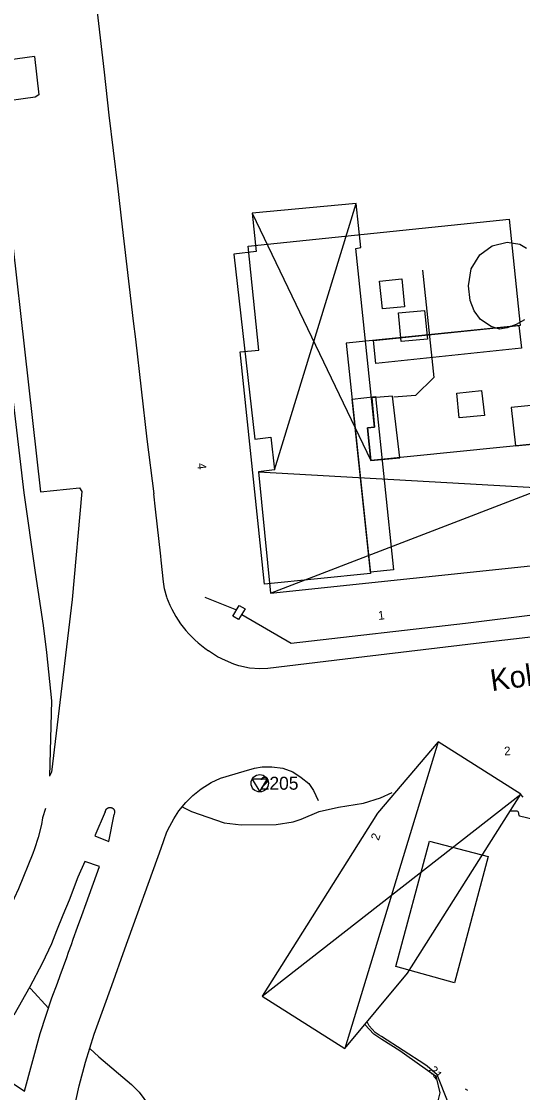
# Model space of a CAD drawing. Extents: x 67169 to 69652, y 20189 to 22818.
# Drawn here: x 69428.4 to 69486.1, y 21189.9 to 21313.4 of the extents above; entities that cross this region are included whole.
import ezdxf

# ---------------------------------------------------------------- set-up
doc = ezdxf.new("R2010")
doc.units = 0
for name, color, linetype in [('BYGGNAD_HUSLIV', 7, 'Continuous'), ('BYGGNAD_HUSLIV 13', 7, 'Continuous'), ('BYGGNADER 263', 7, 'Continuous'), ('BYGGNADSSYMBOLER', 7, 'Continuous'), ('BYGGNADSSYMBOLER 30', 7, 'Continuous'), ('GATUNAMN', 7, 'Continuous'), ('HOJDKURVOR_2014', 7, 'Continuous'), ('HOJDKURVOR_2014 5M', 7, 'Continuous'), ('HOJDKURVOR_TEXTER_2014', 7, 'Continuous'), ('Instruktioner', 7, 'Continuous'), ('Lager 1', 7, 'Continuous'), ('MUR_STAKET', 7, 'Continuous'), ('MUR_STAKET_SYMBOL', 7, 'Continuous'), ('Std_Ritningsstämpel', 7, 'Continuous'), ('STOMPUNKTER', 7, 'Continuous'), ('STOMPUNKTER TEXT', 7, 'Continuous'), ('VAGAR 121', 7, 'Continuous'), ('VAGAR 123', 7, 'Continuous')]:
    doc.layers.add(name, color=color, linetype=linetype)

msp = doc.modelspace()

# ---------------------------------------------------------------- linework, layer by layer
at = {"layer": 'BYGGNAD_HUSLIV'}
for points in [[(69454.5, 21287.53), (69484.59, 21290.62), (69485.84, 21278.39), (69465.81, 21276.32), (69468.6, 21249.77), (69456.36, 21248.52), (69453.59, 21275.32), (69455.74, 21275.54), (69454.5, 21287.53)], [(69469.23, 21273.97), (69468.96, 21276.64), (69485.71, 21278.37), (69485.99, 21275.74), (69469.23, 21273.97)], [(69466.49, 21269.88), (69469.19, 21270.17), (69471.23, 21250.19), (69468.58, 21249.92), (69466.49, 21269.88)], [(69453.46, 21246.09), (69454.14, 21245.68), (69453.39, 21244.45), (69452.71, 21244.86), (69453.46, 21246.09)], [(69475.4, 21218.88), (69482.18, 21217.1), (69478.29, 21202.54), (69471.51, 21204.43), (69475.4, 21218.88)]]:
    msp.add_lwpolyline(points, dxfattribs=at)
at = {"layer": 'BYGGNAD_HUSLIV 13'}
msp.add_lwpolyline([(69454.5, 21287.53), (69484.59, 21290.62), (69485.84, 21278.39), (69465.81, 21276.32), (69468.6, 21249.77), (69456.36, 21248.52), (69453.59, 21275.32), (69455.74, 21275.54), (69454.5, 21287.53)], dxfattribs=at)
at = {"layer": 'BYGGNADER 263'}
msp.add_lwpolyline([(69488.46, 21264.81), (69468.64, 21262.79), (69468.25, 21266.57), (69469.04, 21266.65), (69466.91, 21287.27), (69467.5, 21287.36), (69466.93, 21292.44), (69454.94, 21291.33), (69455.43, 21286.9), (69452.85, 21286.59), (69455.26, 21265.27), (69457.12, 21265.48), (69457.54, 21261.71), (69455.68, 21261.5), (69457.08, 21247.49), (69489.95, 21250.94)], dxfattribs=at)
at = {"layer": 'BYGGNADSSYMBOLER'}
for p, q in [((69457.54, 21261.71), (69466.93, 21292.44)), ((69454.94, 21291.33), (69468.64, 21262.79)), ((69457.08, 21247.49), (69516.13, 21270.28)), ((69455.68, 21261.5), (69517.41, 21257.96)), ((69476.39, 21230.36), (69465.64, 21194.97)), ((69456.1, 21201.01), (69485.94, 21224.32))]:
    msp.add_line(p, q, dxfattribs=at)
at = {"layer": 'BYGGNADSSYMBOLER 30'}
for p, q in [((69457.54, 21261.71), (69466.93, 21292.44)), ((69454.94, 21291.33), (69468.64, 21262.79)), ((69457.08, 21247.49), (69516.13, 21270.28)), ((69455.68, 21261.5), (69517.41, 21257.96)), ((69476.39, 21230.36), (69465.64, 21194.97)), ((69456.1, 21201.01), (69485.94, 21224.32))]:
    msp.add_line(p, q, dxfattribs=at)
at = {"layer": 'HOJDKURVOR_2014'}
for points in [[(69446.88, 21222.84), (69447.97, 21222.31), (69451.72, 21221.02), (69453.67, 21220.77), (69457.71, 21220.82), (69459.68, 21221.12), (69460.62, 21221.42), (69462.69, 21222.3), (69464.89, 21222.82), (69467.78, 21223.26), (69469.75, 21223.87), (69471.08, 21224.51)], [(69484.71, 21222.37), (69485.45, 21222.4), (69485.55, 21222.35), (69485.62, 21222.26), (69485.71, 21221.86), (69485.76, 21221.81), (69490.61, 21220.67)], [(69477.95, 21186.75), (69477.54, 21188.74), (69476.28, 21191.92), (69475.14, 21192.94), (69474.85, 21193.14), (69469.85, 21196.34), (69469.59, 21196.51), (69469.15, 21196.82), (69468.45, 21197.58), (69468.2, 21198.04)]]:
    msp.add_lwpolyline(points, dxfattribs=at)
at = {"layer": 'HOJDKURVOR_2014 5M'}
for points in [[(69485.9, 21224.26), (69486.14, 21223.95)], [(69429.29, 21202.02), (69429.43, 21201.84), (69431.48, 21199.63)], [(69468.49, 21173.6), (69468.64, 21174.08), (69469.65, 21175.83), (69476.38, 21188.93), (69476.63, 21189.84), (69476.2, 21191.61), (69476.1, 21191.76), (69472.79, 21194.13), (69471.96, 21194.7), (69469.89, 21196.01), (69468.98, 21196.62), (69467.94, 21197.74)], [(69436.23, 21194.98), (69437.29, 21193.99), (69441.03, 21190.83), (69441.92, 21189.93), (69443.44, 21187.91)]]:
    msp.add_lwpolyline(points, dxfattribs=at)
at = {"layer": 'Lager 1'}
msp.add_lwpolyline([(69469.65, 21283.49), (69472.2, 21283.77), (69472.53, 21280.52), (69469.98, 21280.29), (69469.65, 21283.49)], dxfattribs=at)
at = {"layer": 'MUR_STAKET'}
for p, q in [((69449.51, 21247.03), (69453.14, 21245.56)), ((69479.52, 21190.31), (69479.79, 21190.15))]:
    msp.add_line(p, q, dxfattribs=at)
for points in [[(69474.61, 21284.76), (69475.91, 21272.37), (69473.78, 21270.3), (69471.28, 21270.09)], [(69453.75, 21245.03), (69459.44, 21241.71), (69479.54, 21244.04), (69487.88, 21245.09), (69496.51, 21246.06), (69512.52, 21247.96)]]:
    msp.add_lwpolyline(points, dxfattribs=at)
at = {"layer": 'MUR_STAKET_SYMBOL'}
for p, q in [((69475.08, 21280.3), (69475.08, 21280.3)), ((69475.55, 21275.84), (69475.55, 21275.84)), ((69475.2, 21271.68), (69475.2, 21271.68)), ((69450.88, 21246.48), (69450.88, 21246.48)), ((69456.45, 21243.45), (69456.45, 21243.45)), ((69479.35, 21244.01), (69479.35, 21244.01)), ((69466.85, 21242.57), (69466.85, 21242.57))]:
    msp.add_line(p, q, dxfattribs=at)
at = {"layer": 'Std_Ritningsstämpel'}
for points in [[(69471.97, 21263.11), (69471.14, 21270.21), (69468.76, 21270.01), (69469.04, 21266.65), (69468.25, 21266.57), (69468.64, 21262.79)], [(69471.14, 21270.21), (69468.76, 21270.01), (69469.04, 21266.65), (69468.25, 21266.57), (69468.64, 21262.79), (69471.97, 21263.11)], [(69485.32, 21264.49), (69488.46, 21264.81), (69488.53, 21264.06), (69492.25, 21264.41), (69492, 21267.17), (69495.2, 21267.57), (69494.9, 21269.93), (69484.8, 21268.92)], [(69485.32, 21264.49), (69488.46, 21264.81), (69488.53, 21264.06), (69492.25, 21264.41), (69492, 21267.17), (69495.2, 21267.57), (69494.9, 21269.93), (69484.8, 21268.92)], [(69476.39, 21230.36), (69469.39, 21222.13), (69456.1, 21201.01), (69465.64, 21194.97), (69472.86, 21203.65), (69485.94, 21224.32)]]:
    msp.add_lwpolyline(points, close=True, dxfattribs=at)
at = {"layer": 'STOMPUNKTER'}
msp.add_lwpolyline([(69455.83, 21224.57), (69456.7, 21226.05), (69454.95, 21226.05)], close=True, dxfattribs=at)
msp.add_circle((69455.83, 21225.57), 1, dxfattribs=at)
at = {"layer": 'VAGAR 121'}
for points in [[(69428.01, 21392.95), (69428.61, 21387.59), (69429.44, 21380.26), (69430.69, 21369.32), (69430.98, 21366.89), (69431.98, 21357.97), (69433.21, 21347.39), (69433.95, 21340.85), (69435.47, 21328.36), (69436.32, 21320.98), (69436.98, 21315.51), (69437.9, 21307.6), (69438.45, 21302.62), (69439.43, 21294.48), (69439.98, 21289.74), (69441.25, 21278.88), (69441.51, 21276.79), (69442.83, 21265.26), (69443.62, 21258.97)], [(69429.85, 21309.41), (69430.35, 21304.99), (69429.94, 21304.72), (69425.48, 21304.11), (69430.55, 21259.19), (69435.06, 21259.63), (69435.32, 21259.22), (69434.2, 21246.77), (69431.81, 21226.86), (69431.6, 21226.4)], [(69445.1, 21247.03), (69444.84, 21247.98), (69444.72, 21248.82), (69444.46, 21251.31), (69444.42, 21251.77), (69443.81, 21257.18), (69443.62, 21258.97)], [(69517.65, 21246.44), (69516.83, 21246.13), (69516.14, 21245.92), (69515.21, 21245.75), (69514.19, 21245.63), (69510.39, 21245.17), (69508.74, 21244.98), (69501.92, 21244.18), (69495.7, 21243.43), (69481.45, 21241.76), (69467.89, 21240.15), (69456.77, 21238.8), (69455.83, 21238.77), (69454.64, 21238.86), (69453.42, 21239.1), (69452.85, 21239.32), (69451.88, 21239.72), (69450.95, 21240.15), (69449.91, 21240.85)], [(69434.4, 21187.86), (69435.01, 21190.68), (69435.73, 21193.38), (69436.74, 21196.62), (69437.83, 21199.57), (69438.78, 21202.24), (69440.29, 21206.48), (69444.47, 21218.09), (69444.78, 21218.98), (69445.11, 21219.95), (69445.45, 21220.63), (69445.91, 21221.45), (69446.5, 21222.39), (69447.31, 21223.34), (69448.13, 21224.15), (69449.09, 21224.93), (69450.24, 21225.64), (69451.31, 21226.14), (69454.03, 21226.97), (69455.22, 21227.29), (69456.09, 21227.47), (69457.24, 21227.48), (69458.48, 21227.31), (69459.66, 21226.87), (69460.61, 21226.25), (69461.48, 21225.53), (69462.02, 21224.74), (69462.57, 21223.59)], [(69431.13, 21222.66), (69430.79, 21221.58), (69430.66, 21220.81), (69430.28, 21219.3), (69429.85, 21218), (69429.66, 21217.46), (69428, 21213.37), (69427.01, 21211.24), (69426.66, 21210.54), (69422.06, 21202.37), (69418.54, 21198.14), (69417.09, 21196.79), (69416.09, 21195.97), (69414.59, 21194.78)], [(69438, 21222.27), (69438.08, 21222.45), (69438.09, 21222.46), (69438.09, 21222.48), (69438.1, 21222.5), (69438.11, 21222.51), (69438.13, 21222.54), (69438.14, 21222.56), (69438.15, 21222.58), (69438.16, 21222.59), (69438.18, 21222.61), (69438.19, 21222.63), (69438.21, 21222.64), (69438.22, 21222.65), (69438.24, 21222.66), (69438.26, 21222.68), (69438.28, 21222.69), (69438.3, 21222.71), (69438.33, 21222.73), (69438.35, 21222.73), (69438.37, 21222.74), (69438.39, 21222.75), (69438.41, 21222.76), (69438.43, 21222.76), (69438.45, 21222.77), (69438.48, 21222.77), (69438.51, 21222.78), (69438.54, 21222.78), (69438.56, 21222.78), (69438.58, 21222.78), (69438.59, 21222.78), (69438.6, 21222.78), (69438.63, 21222.78), (69438.64, 21222.78), (69438.66, 21222.78), (69438.67, 21222.77), (69438.69, 21222.77), (69438.71, 21222.76), (69438.73, 21222.76), (69438.75, 21222.75), (69438.76, 21222.74), (69438.79, 21222.73), (69438.81, 21222.72), (69438.82, 21222.72), (69438.84, 21222.71), (69438.86, 21222.69), (69438.87, 21222.69), (69438.88, 21222.68), (69438.89, 21222.67), (69438.9, 21222.67), (69438.91, 21222.66), (69438.92, 21222.65), (69438.93, 21222.64), (69438.93, 21222.64), (69438.95, 21222.62), (69438.96, 21222.61), (69438.96, 21222.61), (69438.97, 21222.59), (69438.98, 21222.58), (69438.99, 21222.57), (69439, 21222.56), (69439.01, 21222.55), (69439.02, 21222.53), (69439.03, 21222.52), (69439.03, 21222.51), (69439.04, 21222.49), (69439.05, 21222.47), (69439.05, 21222.46), (69439.06, 21222.45), (69439.07, 21222.43), (69439.07, 21222.41), (69439.08, 21222.39), (69439.08, 21222.36), (69439.08, 21222.35), (69439.09, 21222.35), (69439.09, 21222.34), (69439.09, 21222.33), (69439.09, 21222.33), (69439.09, 21222.33), (69439.09, 21222.32), (69439.09, 21222.31), (69439.09, 21222.3), (69439.09, 21222.29), (69439.09, 21222.27), (69439.1, 21222.25), (69439.1, 21222.24), (69439.1, 21222.23), (69439.1, 21222.23), (69439.1, 21222.22), (69439.09, 21222.21), (69439.09, 21222.21), (69439.05, 21221.96)], [(69438, 21222.27), (69436.8, 21219.51), (69438.45, 21218.85), (69439.05, 21221.96)], [(69423.83, 21193.31), (69428.71, 21190.06), (69430.53, 21196.7), (69431.87, 21200.83), (69432.51, 21202.49), (69432.82, 21203.39), (69433.58, 21205.46), (69433.8, 21206.09), (69434.11, 21206.98), (69434.33, 21207.6), (69434.82, 21208.98), (69435.31, 21210.31), (69435.8, 21211.68), (69437.37, 21215.96), (69435.66, 21216.53), (69434.87, 21214.74), (69433.84, 21212.09), (69433.14, 21210.34), (69432.41, 21208.53), (69431.84, 21207.06), (69430.76, 21204.76)], [(69430.76, 21204.76), (69429.33, 21202.09), (69427.47, 21198.83)]]:
    msp.add_lwpolyline(points, dxfattribs=at)
msp.add_arc((69456.93, 21251.28), 12.57, 199.7358, 236.0321, dxfattribs=at)
at = {"layer": 'VAGAR 123'}
for points in [[(69429.85, 21309.41), (69425.63, 21308.81), (69423.31, 21308.4), (69422.71, 21307.31), (69423.24, 21303.83), (69424.98, 21289.32), (69426.54, 21276.78), (69428.64, 21259.05), (69429.95, 21249.89), (69430.86, 21243.78), (69431.23, 21240.65), (69431.82, 21235.06), (69431.6, 21226.4)], [(69486.35, 21279.01), (69485.38, 21278.49), (69484.37, 21278.09), (69483.46, 21277.95), (69482.52, 21278.24), (69481.28, 21279.07), (69480.53, 21280.07), (69480.07, 21281.27), (69479.91, 21282.93), (69480.22, 21284.91), (69481.19, 21286.51), (69482.63, 21287.55), (69484.35, 21287.99), (69485.82, 21287.74), (69486.6, 21287.3)], [(69472.15, 21276.52), (69471.81, 21279.82), (69474.82, 21280.09), (69475.16, 21276.81), (69472.15, 21276.52)], [(69478.81, 21267.72), (69478.54, 21270.57), (69481.39, 21270.87), (69481.73, 21267.99), (69478.81, 21267.72)]]:
    msp.add_lwpolyline(points, dxfattribs=at)

# ---------------------------------------------------------------- texts
at = {"layer": 'GATUNAMN'}
msp.add_text('Kolonivägen', height=2.5, rotation=7.9373, dxfattribs=at).set_placement((69482.58, 21236.18))
at = {"layer": 'HOJDKURVOR_TEXTER_2014'}
msp.add_text('21', height=1, rotation=308.596, dxfattribs=at).set_placement((69475.25, 21192.47))
at = {"layer": 'Instruktioner'}
for s, rotation, p in [('4', 276.7912, (69448.61, 21262.45)), ('1', 6.8442, (69469.53, 21244.4)), ('2', 3.5053, (69484.03, 21228.77)), ('2', 70.3506, (69469.53, 21218.89))]:
    msp.add_text(s, height=1, rotation=rotation, dxfattribs=at).set_placement(p)
at = {"layer": 'STOMPUNKTER TEXT'}
msp.add_text('2205', height=1.5, dxfattribs=at).set_placement((69455.83, 21224.82))

doc.saveas('drawing.dxf')
